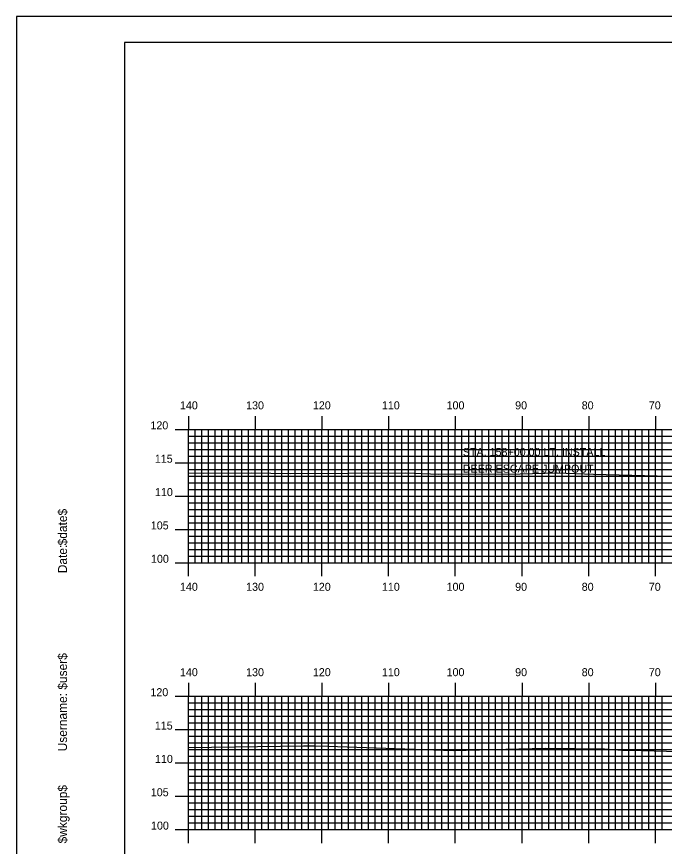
# Model space of a CAD drawing. Extents: x 1779499 to 1779842, y 442591 to 442811.
# Drawn here: x 1779499.1 to 1779596.2, y 442686.2 to 442810.5 of the extents above; entities that cross this region are included whole.
import ezdxf

# ---------------------------------------------------------------- set-up
doc = ezdxf.new("R2010")
doc.units = 0
for name, color, linetype in [('BORDER', 7, 'Continuous'), ('D_Text_Standard', 7, 'Continuous'), ('H_V ANNOTATION', 7, 'Continuous'), ('MAJOR', 7, 'Continuous'), ('MINOR', 7, 'Continuous'), ('PLOT BOUNDARY', 7, 'Continuous'), ('S_Roadway_Centerline', 7, 'Continuous')]:
    doc.layers.add(name, color=color, linetype=linetype)

msp = doc.modelspace()

# ---------------------------------------------------------------- linework, layer by layer
at = {"layer": 'BORDER'}
msp.add_lwpolyline([(1779515.24, 442596.67), (1779835.24, 442596.67), (1779835.24, 442806.67), (1779515.24, 442806.67)], close=True, dxfattribs=at)
at = {"layer": 'MAJOR'}
for p, q in [((1779524.84, 442750.67), (1779524.84, 442748.67)), ((1779534.84, 442750.67), (1779534.84, 442748.67)), ((1779544.84, 442750.67), (1779544.84, 442748.67)), ((1779554.84, 442750.67), (1779554.84, 442748.67)), ((1779564.84, 442750.67), (1779564.84, 442748.67)), ((1779574.84, 442750.67), (1779574.84, 442748.67)), ((1779584.84, 442750.67), (1779584.84, 442748.67)), ((1779594.84, 442750.67), (1779594.84, 442748.67)), ((1779522.84, 442748.67), (1779524.84, 442748.67)), ((1779524.84, 442748.67), (1779804.84, 442748.67)), ((1779524.84, 442728.67), (1779524.84, 442748.67)), ((1779524.84, 442728.67), (1779524.84, 442748.67)), ((1779524.84, 442748.67), (1779804.84, 442748.67)), ((1779534.84, 442728.67), (1779534.84, 442748.67)), ((1779544.84, 442728.67), (1779544.84, 442748.67)), ((1779554.84, 442728.67), (1779554.84, 442748.67)), ((1779564.84, 442728.67), (1779564.84, 442748.67)), ((1779574.84, 442728.67), (1779574.84, 442748.67)), ((1779584.84, 442728.67), (1779584.84, 442748.67)), ((1779594.84, 442728.67), (1779594.84, 442748.67)), ((1779522.84, 442743.67), (1779524.84, 442743.67)), ((1779524.84, 442743.67), (1779804.84, 442743.67)), ((1779522.84, 442738.67), (1779524.84, 442738.67)), ((1779524.84, 442738.67), (1779804.84, 442738.67)), ((1779522.84, 442733.67), (1779524.84, 442733.67)), ((1779524.84, 442733.67), (1779804.84, 442733.67)), ((1779522.84, 442728.67), (1779524.84, 442728.67)), ((1779524.84, 442728.67), (1779804.84, 442728.67)), ((1779524.84, 442728.67), (1779804.84, 442728.67)), ((1779524.84, 442726.66), (1779524.84, 442728.67)), ((1779534.84, 442726.66), (1779534.84, 442728.67)), ((1779544.84, 442726.66), (1779544.84, 442728.67)), ((1779554.84, 442726.66), (1779554.84, 442728.67)), ((1779564.84, 442726.66), (1779564.84, 442728.67)), ((1779574.84, 442726.66), (1779574.84, 442728.67)), ((1779584.84, 442726.66), (1779584.84, 442728.67)), ((1779594.84, 442726.66), (1779594.84, 442728.67)), ((1779524.84, 442710.67), (1779524.84, 442708.67)), ((1779534.84, 442710.67), (1779534.84, 442708.67)), ((1779544.84, 442710.67), (1779544.84, 442708.67)), ((1779554.84, 442710.67), (1779554.84, 442708.67)), ((1779564.84, 442710.67), (1779564.84, 442708.67)), ((1779574.84, 442710.67), (1779574.84, 442708.67)), ((1779584.84, 442710.67), (1779584.84, 442708.67)), ((1779594.84, 442710.67), (1779594.84, 442708.67)), ((1779522.84, 442708.67), (1779524.84, 442708.67)), ((1779524.84, 442708.67), (1779804.84, 442708.67)), ((1779524.84, 442688.67), (1779524.84, 442708.67)), ((1779524.84, 442688.67), (1779524.84, 442708.67)), ((1779524.84, 442708.67), (1779804.84, 442708.67)), ((1779534.84, 442688.67), (1779534.84, 442708.67)), ((1779544.84, 442688.67), (1779544.84, 442708.67)), ((1779554.84, 442688.67), (1779554.84, 442708.67)), ((1779564.84, 442688.67), (1779564.84, 442708.67)), ((1779574.84, 442688.67), (1779574.84, 442708.67)), ((1779584.84, 442688.67), (1779584.84, 442708.67)), ((1779594.84, 442688.67), (1779594.84, 442708.67)), ((1779522.84, 442703.67), (1779524.84, 442703.67)), ((1779524.84, 442703.67), (1779804.84, 442703.67)), ((1779522.84, 442698.67), (1779524.84, 442698.67)), ((1779524.84, 442698.67), (1779804.84, 442698.67)), ((1779522.84, 442693.67), (1779524.84, 442693.67)), ((1779524.84, 442693.67), (1779804.84, 442693.67)), ((1779522.84, 442688.67), (1779524.84, 442688.67)), ((1779524.84, 442688.67), (1779804.84, 442688.67)), ((1779524.84, 442688.67), (1779804.84, 442688.67)), ((1779524.84, 442686.66), (1779524.84, 442688.67)), ((1779534.84, 442686.66), (1779534.84, 442688.67)), ((1779544.84, 442686.66), (1779544.84, 442688.67)), ((1779554.84, 442686.66), (1779554.84, 442688.67)), ((1779564.84, 442686.66), (1779564.84, 442688.67)), ((1779574.84, 442686.66), (1779574.84, 442688.67)), ((1779584.84, 442686.66), (1779584.84, 442688.67)), ((1779594.84, 442686.66), (1779594.84, 442688.67))]:
    msp.add_line(p, q, dxfattribs=at)
at = {"layer": 'MINOR'}
for p, q in [((1779525.84, 442728.67), (1779525.84, 442748.67)), ((1779526.84, 442728.67), (1779526.84, 442748.67)), ((1779527.84, 442728.67), (1779527.84, 442748.67)), ((1779528.84, 442728.67), (1779528.84, 442748.67)), ((1779529.84, 442728.67), (1779529.84, 442748.67)), ((1779530.84, 442728.67), (1779530.84, 442748.67)), ((1779531.84, 442728.67), (1779531.84, 442748.67)), ((1779532.84, 442728.67), (1779532.84, 442748.67)), ((1779533.84, 442728.67), (1779533.84, 442748.67)), ((1779535.84, 442728.67), (1779535.84, 442748.67)), ((1779536.84, 442728.67), (1779536.84, 442748.67)), ((1779537.84, 442728.67), (1779537.84, 442748.67)), ((1779538.84, 442728.67), (1779538.84, 442748.67)), ((1779539.84, 442728.67), (1779539.84, 442748.67)), ((1779540.84, 442728.67), (1779540.84, 442748.67)), ((1779541.84, 442728.67), (1779541.84, 442748.67)), ((1779542.84, 442728.67), (1779542.84, 442748.67)), ((1779543.84, 442728.67), (1779543.84, 442748.67)), ((1779545.84, 442728.67), (1779545.84, 442748.67)), ((1779546.84, 442728.67), (1779546.84, 442748.67)), ((1779547.84, 442728.67), (1779547.84, 442748.67)), ((1779548.84, 442728.67), (1779548.84, 442748.67)), ((1779549.84, 442728.67), (1779549.84, 442748.67)), ((1779550.84, 442728.67), (1779550.84, 442748.67)), ((1779551.84, 442728.67), (1779551.84, 442748.67)), ((1779552.84, 442728.67), (1779552.84, 442748.67)), ((1779553.84, 442728.67), (1779553.84, 442748.67)), ((1779555.84, 442728.67), (1779555.84, 442748.67)), ((1779556.84, 442728.67), (1779556.84, 442748.67)), ((1779557.84, 442728.67), (1779557.84, 442748.67)), ((1779558.84, 442728.67), (1779558.84, 442748.67)), ((1779559.84, 442728.67), (1779559.84, 442748.67)), ((1779560.84, 442728.67), (1779560.84, 442748.67)), ((1779561.84, 442728.67), (1779561.84, 442748.67)), ((1779562.84, 442728.67), (1779562.84, 442748.67)), ((1779563.84, 442728.67), (1779563.84, 442748.67)), ((1779565.84, 442728.67), (1779565.84, 442748.67)), ((1779566.84, 442728.67), (1779566.84, 442748.67)), ((1779567.84, 442728.67), (1779567.84, 442748.67)), ((1779568.84, 442728.67), (1779568.84, 442748.67)), ((1779569.84, 442728.67), (1779569.84, 442748.67)), ((1779570.84, 442728.67), (1779570.84, 442748.67)), ((1779571.84, 442728.67), (1779571.84, 442748.67)), ((1779572.84, 442728.67), (1779572.84, 442748.67)), ((1779573.84, 442728.67), (1779573.84, 442748.67)), ((1779575.84, 442728.67), (1779575.84, 442748.67)), ((1779576.84, 442728.67), (1779576.84, 442748.67)), ((1779577.84, 442728.67), (1779577.84, 442748.67)), ((1779578.84, 442728.67), (1779578.84, 442748.67)), ((1779579.84, 442728.67), (1779579.84, 442748.67)), ((1779580.84, 442728.67), (1779580.84, 442748.67)), ((1779581.84, 442728.67), (1779581.84, 442748.67)), ((1779582.84, 442728.67), (1779582.84, 442748.67)), ((1779583.84, 442728.67), (1779583.84, 442748.67)), ((1779585.84, 442728.67), (1779585.84, 442748.67)), ((1779586.84, 442728.67), (1779586.84, 442748.67)), ((1779587.84, 442728.67), (1779587.84, 442748.67)), ((1779588.84, 442728.67), (1779588.84, 442748.67)), ((1779589.84, 442728.67), (1779589.84, 442748.67)), ((1779590.84, 442728.67), (1779590.84, 442748.67)), ((1779591.84, 442728.67), (1779591.84, 442748.67)), ((1779592.84, 442728.67), (1779592.84, 442748.67)), ((1779593.84, 442728.67), (1779593.84, 442748.67)), ((1779595.84, 442728.67), (1779595.84, 442748.67)), ((1779524.84, 442747.67), (1779804.84, 442747.67)), ((1779524.84, 442747.67), (1779526.85, 442747.67)), ((1779524.84, 442746.67), (1779804.84, 442746.67)), ((1779524.84, 442746.67), (1779526.85, 442746.67)), ((1779524.84, 442745.67), (1779804.84, 442745.67)), ((1779524.84, 442745.67), (1779526.85, 442745.67)), ((1779524.84, 442744.67), (1779804.84, 442744.67)), ((1779524.84, 442744.67), (1779526.85, 442744.67)), ((1779524.84, 442742.67), (1779804.84, 442742.67)), ((1779524.84, 442742.67), (1779526.85, 442742.67)), ((1779524.84, 442741.67), (1779804.84, 442741.67)), ((1779524.84, 442741.67), (1779526.85, 442741.67)), ((1779524.84, 442740.67), (1779804.84, 442740.67)), ((1779524.84, 442740.67), (1779526.85, 442740.67)), ((1779524.84, 442739.67), (1779804.84, 442739.67)), ((1779524.84, 442739.67), (1779526.85, 442739.67)), ((1779524.84, 442737.67), (1779804.84, 442737.67)), ((1779524.84, 442737.67), (1779526.85, 442737.67)), ((1779524.84, 442736.67), (1779804.84, 442736.67)), ((1779524.84, 442736.67), (1779526.85, 442736.67)), ((1779524.84, 442735.67), (1779804.84, 442735.67)), ((1779524.84, 442735.67), (1779526.85, 442735.67)), ((1779524.84, 442734.67), (1779804.84, 442734.67)), ((1779524.84, 442734.67), (1779526.85, 442734.67)), ((1779524.84, 442732.67), (1779804.84, 442732.67)), ((1779524.84, 442732.67), (1779526.85, 442732.67)), ((1779524.84, 442731.67), (1779804.84, 442731.67)), ((1779524.84, 442731.67), (1779526.85, 442731.67)), ((1779524.84, 442730.67), (1779804.84, 442730.67)), ((1779524.84, 442730.67), (1779526.85, 442730.67)), ((1779524.84, 442729.67), (1779804.84, 442729.67)), ((1779524.84, 442729.67), (1779526.85, 442729.67)), ((1779525.84, 442688.67), (1779525.84, 442708.67)), ((1779526.84, 442688.67), (1779526.84, 442708.67)), ((1779527.84, 442688.67), (1779527.84, 442708.67)), ((1779528.84, 442688.67), (1779528.84, 442708.67)), ((1779529.84, 442688.67), (1779529.84, 442708.67)), ((1779530.84, 442688.67), (1779530.84, 442708.67)), ((1779531.84, 442688.67), (1779531.84, 442708.67)), ((1779532.84, 442688.67), (1779532.84, 442708.67)), ((1779533.84, 442688.67), (1779533.84, 442708.67)), ((1779535.84, 442688.67), (1779535.84, 442708.67)), ((1779536.84, 442688.67), (1779536.84, 442708.67)), ((1779537.84, 442688.67), (1779537.84, 442708.67)), ((1779538.84, 442688.67), (1779538.84, 442708.67)), ((1779539.84, 442688.67), (1779539.84, 442708.67)), ((1779540.84, 442688.67), (1779540.84, 442708.67)), ((1779541.84, 442688.67), (1779541.84, 442708.67)), ((1779542.84, 442688.67), (1779542.84, 442708.67)), ((1779543.84, 442688.67), (1779543.84, 442708.67)), ((1779545.84, 442688.67), (1779545.84, 442708.67)), ((1779546.84, 442688.67), (1779546.84, 442708.67)), ((1779547.84, 442688.67), (1779547.84, 442708.67)), ((1779548.84, 442688.67), (1779548.84, 442708.67)), ((1779549.84, 442688.67), (1779549.84, 442708.67)), ((1779550.84, 442688.67), (1779550.84, 442708.67)), ((1779551.84, 442688.67), (1779551.84, 442708.67)), ((1779552.84, 442688.67), (1779552.84, 442708.67)), ((1779553.84, 442688.67), (1779553.84, 442708.67)), ((1779555.84, 442688.67), (1779555.84, 442708.67)), ((1779556.84, 442688.67), (1779556.84, 442708.67)), ((1779557.84, 442688.67), (1779557.84, 442708.67)), ((1779558.84, 442688.67), (1779558.84, 442708.67)), ((1779559.84, 442688.67), (1779559.84, 442708.67)), ((1779560.84, 442688.67), (1779560.84, 442708.67)), ((1779561.84, 442688.67), (1779561.84, 442708.67)), ((1779562.84, 442688.67), (1779562.84, 442708.67)), ((1779563.84, 442688.67), (1779563.84, 442708.67)), ((1779565.84, 442688.67), (1779565.84, 442708.67)), ((1779566.84, 442688.67), (1779566.84, 442708.67)), ((1779567.84, 442688.67), (1779567.84, 442708.67)), ((1779568.84, 442688.67), (1779568.84, 442708.67)), ((1779569.84, 442688.67), (1779569.84, 442708.67)), ((1779570.84, 442688.67), (1779570.84, 442708.67)), ((1779571.84, 442688.67), (1779571.84, 442708.67)), ((1779572.84, 442688.67), (1779572.84, 442708.67)), ((1779573.84, 442688.67), (1779573.84, 442708.67)), ((1779575.84, 442688.67), (1779575.84, 442708.67)), ((1779576.84, 442688.67), (1779576.84, 442708.67)), ((1779577.84, 442688.67), (1779577.84, 442708.67)), ((1779578.84, 442688.67), (1779578.84, 442708.67)), ((1779579.84, 442688.67), (1779579.84, 442708.67)), ((1779580.84, 442688.67), (1779580.84, 442708.67)), ((1779581.84, 442688.67), (1779581.84, 442708.67)), ((1779582.84, 442688.67), (1779582.84, 442708.67)), ((1779583.84, 442688.67), (1779583.84, 442708.67)), ((1779585.84, 442688.67), (1779585.84, 442708.67)), ((1779586.84, 442688.67), (1779586.84, 442708.67)), ((1779587.84, 442688.67), (1779587.84, 442708.67)), ((1779588.84, 442688.67), (1779588.84, 442708.67)), ((1779589.84, 442688.67), (1779589.84, 442708.67)), ((1779590.84, 442688.67), (1779590.84, 442708.67)), ((1779591.84, 442688.67), (1779591.84, 442708.67)), ((1779592.84, 442688.67), (1779592.84, 442708.67)), ((1779593.84, 442688.67), (1779593.84, 442708.67)), ((1779595.84, 442688.67), (1779595.84, 442708.67)), ((1779524.84, 442707.67), (1779804.84, 442707.67)), ((1779524.84, 442707.67), (1779526.85, 442707.67)), ((1779524.84, 442706.67), (1779804.84, 442706.67)), ((1779524.84, 442706.67), (1779526.85, 442706.67)), ((1779524.84, 442705.67), (1779804.84, 442705.67)), ((1779524.84, 442705.67), (1779526.85, 442705.67)), ((1779524.84, 442704.67), (1779804.84, 442704.67)), ((1779524.84, 442704.67), (1779526.85, 442704.67)), ((1779524.84, 442702.67), (1779804.84, 442702.67)), ((1779524.84, 442702.67), (1779526.85, 442702.67)), ((1779524.84, 442701.67), (1779804.84, 442701.67)), ((1779524.84, 442701.67), (1779526.85, 442701.67)), ((1779524.84, 442700.67), (1779804.84, 442700.67)), ((1779524.84, 442700.67), (1779526.85, 442700.67)), ((1779524.84, 442699.67), (1779804.84, 442699.67)), ((1779524.84, 442699.67), (1779526.85, 442699.67)), ((1779524.84, 442697.67), (1779804.84, 442697.67)), ((1779524.84, 442697.67), (1779526.85, 442697.67)), ((1779524.84, 442696.67), (1779804.84, 442696.67)), ((1779524.84, 442696.67), (1779526.85, 442696.67)), ((1779524.84, 442695.67), (1779804.84, 442695.67)), ((1779524.84, 442695.67), (1779526.85, 442695.67)), ((1779524.84, 442694.67), (1779804.84, 442694.67)), ((1779524.84, 442694.67), (1779526.85, 442694.67)), ((1779524.84, 442692.67), (1779804.84, 442692.67)), ((1779524.84, 442692.67), (1779526.85, 442692.67)), ((1779524.84, 442691.67), (1779804.84, 442691.67)), ((1779524.84, 442691.67), (1779526.85, 442691.67)), ((1779524.84, 442690.67), (1779804.84, 442690.67)), ((1779524.84, 442690.67), (1779526.85, 442690.67)), ((1779524.84, 442689.67), (1779804.84, 442689.67)), ((1779524.84, 442689.67), (1779526.85, 442689.67))]:
    msp.add_line(p, q, dxfattribs=at)
at = {"layer": 'PLOT BOUNDARY'}
msp.add_lwpolyline([(1779499.06, 442590.55), (1779839.06, 442590.55), (1779839.06, 442810.55), (1779499.06, 442810.55)], close=True, dxfattribs=at)
at = {"layer": 'S_Roadway_Centerline'}
for points in [[(1779524.84, 442742.15), (1779527.11, 442742.1), (1779534.25, 442742.17), (1779540.12, 442742.04), (1779557.42, 442742.13), (1779562.37, 442741.93), (1779574.56, 442742.01), (1779580.09, 442742.15), (1779585.54, 442741.94), (1779598.93, 442741.61)], [(1779524.84, 442700.98), (1779542.07, 442701.21), (1779543.7, 442701.23), (1779545.73, 442701.17), (1779564.52, 442700.55), (1779578.32, 442700.89), (1779587.23, 442700.78), (1779589.84, 442700.56), (1779592.77, 442700.52), (1779602.15, 442700.3), (1779609.24, 442700.21), (1779617.64, 442700.19), (1779633.75, 442699.89), (1779636.78, 442699.8), (1779640.23, 442699.7), (1779648.88, 442699.52), (1779656.08, 442699.28), (1779664.38, 442699.29), (1779678.74, 442699.37), (1779688.72, 442699.14), (1779695.35, 442698.99), (1779700.89, 442698.9), (1779712.94, 442698.94), (1779723.89, 442699.2)]]:
    msp.add_lwpolyline(points, dxfattribs=at)

# ---------------------------------------------------------------- texts
at = {"layer": 'BORDER'}
for s, p in [('$date$', (1779506.61, 442731.28)), ('Date:', (1779506.61, 442727.1)), ('$user$', (1779506.61, 442709.65)), ('Username:', (1779506.61, 442700.4)), ('$wkgroup$', (1779506.61, 442686.6))]:
    msp.add_text(s, height=1.339, rotation=90, dxfattribs=at).set_placement(p)
at = {"layer": 'D_Text_Standard'}
for s, p in [('STA. 158+00.00 LT. INSTALL ', (1779565.97, 442744.68)), ('DEER ESCAPE JUMPOUT', (1779565.97, 442742.18))]:
    msp.add_text(s, height=1.2, dxfattribs=at).set_placement(p)
at = {"layer": 'H_V ANNOTATION'}
for s, p in [('140', (1779523.55, 442751.67)), ('130', (1779533.47, 442751.67)), ('120', (1779543.48, 442751.67)), ('110', (1779553.83, 442751.67)), ('100', (1779563.53, 442751.67)), ('90', (1779573.81, 442751.67)), ('80', (1779583.79, 442751.67)), ('70', (1779593.85, 442751.67)), ('120', (1779519.12, 442748.67)), ('115', (1779519.78, 442743.67)), ('110', (1779519.81, 442738.67)), ('105', (1779519.18, 442733.67)), ('100', (1779519.21, 442728.67)), ('140', (1779523.55, 442724.47)), ('130', (1779533.47, 442724.47)), ('120', (1779543.48, 442724.47)), ('110', (1779553.83, 442724.47)), ('100', (1779563.53, 442724.47)), ('90', (1779573.81, 442724.47)), ('80', (1779583.79, 442724.47)), ('70', (1779593.85, 442724.47)), ('140', (1779523.55, 442711.67)), ('130', (1779533.47, 442711.67)), ('120', (1779543.48, 442711.67)), ('110', (1779553.83, 442711.67)), ('100', (1779563.53, 442711.67)), ('90', (1779573.81, 442711.67)), ('80', (1779583.79, 442711.67)), ('70', (1779593.85, 442711.67)), ('120', (1779519.12, 442708.67)), ('115', (1779519.78, 442703.67)), ('110', (1779519.81, 442698.67)), ('105', (1779519.18, 442693.67)), ('100', (1779519.21, 442688.67))]:
    msp.add_text(s, height=1.2, dxfattribs=at).set_placement(p)
at = {"layer": 'MAJOR'}
for p in [(1779524.83, 442728.67), (1779524.83, 442688.67)]:
    msp.add_text('-', height=0.012, dxfattribs=at).set_placement(p)

doc.saveas('drawing.dxf')
